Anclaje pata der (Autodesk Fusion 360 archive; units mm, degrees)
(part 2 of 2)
sketch "Boceto32" plane through (0, 285, 0) normal (0, 1, 0) x axis (1, 0, 0)
  circle C1 centre (0, 0) radius 7
  circle C2 centre (0, 0) radius 5.25
  point P1 (0, 0)
  point P2 (0, 0)
  coincident P1 P2
  concentric C1 C2
  dimension "d256" diameter C1 = 14 (= "d_29")
  dimension "d257" diameter C2 = 10.5 (= "d_29_int")
sketch "Boceto33" plane through (0, 0, 0) normal (0, 0, 1) x axis (1, 0, 0)
  line L1 (47.25, -30) -> (45.5, -30)
  line L2 (45.5, -27) -> (47.25, -27)
  line L3 (50.75, -20) -> (49, -20)
  line L4 (49, -17) -> (50.75, -17)
  line L5 (54.25, -10) -> (52.5, -10)
  line L6 (52.5, -7) -> (54.25, -7)
  line L7 (56, 0) -> (54.25, 0)
  line L8 (54.25, 3) -> (56, 3)
  line L9 (52.5, 10) -> (50.75, 10)
  line L10 (50.75, 13) -> (52.5, 13)
  line L11 (49, 20) -> (47.25, 20)
  line L12 (47.25, 23) -> (49, 23)
  line L13 (45.5, 30) -> (43.75, 30)
  line L14 (43.75, 33) -> (45.5, 33)
  line L15 (43.75, 40) -> (42, 40)
  line L16 (42, 43) -> (43.75, 43)
  line L17 (42, 50) -> (40.25, 50)
  line L18 (40.25, 53) -> (42, 53)
  line L19 (40.25, 60) -> (38.5, 60)
  line L20 (38.5, 63) -> (40.25, 63)
  line L21 (38.5, 70) -> (36.75, 70)
  line L22 (36.75, 73) -> (38.5, 73)
  line L23 (29.75, 80) -> (28, 80)
  line L24 (28, 83) -> (29.75, 83)
  line L25 (22.75, 90) -> (21, 90)
  line L26 (21, 93) -> (22.75, 93)
  line L27 (45.5, -30) -> (47.25, -30)
  line L28 (45.5, -27) -> (45.5, -30)
  line L29 (49, -20) -> (50.75, -20)
  line L30 (49, -17) -> (49, -20)
  line L31 (50.75, -17) -> (49, -17)
  line L32 (52.5, -10) -> (54.25, -10)
  line L33 (52.5, -10) -> (54.25, -10)
  line L34 (52.5, -7) -> (52.5, -10)
  line L35 (54.25, 0) -> (56, 0)
  line L36 (54.25, 0) -> (56, 0)
  line L37 (54.25, 3) -> (54.25, 0)
  line L38 (50.75, 10) -> (52.5, 10)
  line L39 (50.75, 13) -> (50.75, 10)
  line L40 (47.25, 20) -> (49, 20)
  line L41 (43.75, 30) -> (45.5, 30)
  line L42 (43.75, 33) -> (43.75, 30)
  line L43 (42, 40) -> (43.75, 40)
  line L44 (42, 43) -> (42, 40)
  line L45 (40.25, 50) -> (42, 50)
  line L46 (38.5, 60) -> (40.25, 60)
  line L47 (38.5, 63) -> (40.25, 63)
  line L48 (36.75, 70) -> (38.5, 70)
  line L49 (36.75, 73) -> (36.75, 70)
  line L50 (38.5, 60) -> (38.5, 63)
  line L51 (40.25, 53) -> (40.25, 50)
  line L52 (38.5, 73) -> (36.75, 75)
  line L53 (28, 80) -> (29.75, 80)
  line L54 (29.75, 83) -> (28, 85)
  line L55 (21, 90) -> (22.75, 90)
  line L56 (21, 93) -> (21, 90)
  line L57 (28, 83) -> (28, 80)
  line L58 (47.25, 23) -> (47.25, 20)
  line L59 (17, 88) -> (17, 90)
  line L60 (41.5, -32) -> (41.5, -25)
  line L61 (2, 90) -> (2, 95)
  line L62 (17, 90) -> (2, 90)
  line L63 (2, 100) -> (2, 95)
  line L64 (5, 100) -> (2, 100)
  line L65 (5, 96) -> (5, 100)
  line L66 (41.5, -37) -> (41.5, -32)
  line L67 (44.5, -37) -> (41.5, -37)
  line L68 (45.5, -37) -> (44.5, -37)
  line L69 (47.25, -38.2302) -> (47.25, -30)
  line L70 (47.25, -37) -> (45.5, -37)
  arc A1 centre (-131.6173, -3.3783) radius 174.4624 clockwise from (17, 88) to (41.5, -25)
  arc A2 centre (-12.1249, 48.1252) radius 54.4955 clockwise from (22.75, 90) to (29.75, 83)
  arc A3 centre (19.2917, 57.9584) radius 24.3969 clockwise from (29.75, 80) to (38.5, 73)
  arc A4 centre (-26.7489, 49.969) radius 68.2544 clockwise from (38.5, 70) to (40.25, 63)
  arc A5 centre (-76.2927, 27.1457) radius 121.0852 clockwise from (40.25, 60) to (42, 53)
  arc A6 centre (22.875, 41.5) radius 20.9289 clockwise from (42, 50) to (43.75, 43)
  arc A7 centre (-1.5, 24.9688) radius 47.6812 clockwise from (43.75, 40) to (45.5, 33)
  arc A8 centre (19.0393, 12.3947) radius 31.7823 clockwise from (45.5, 30) to (49, 23)
  arc A9 centre (-15.6248, -16.6874) radius 74.3124 clockwise from (49, 20) to (52.5, 13)
  arc A10 centre (40.625, -0.3125) radius 15.7278 clockwise from (52.5, 10) to (56, 3)
  arc A11 centre (21.7396, 4.8464) radius 34.6015 clockwise from (56, 0) to (54.25, -7)
  arc A12 centre (24.9327, 0.2836) radius 31.0686 clockwise from (54.25, -10) to (50.75, -17)
  arc A13 centre (-15.8334, 8.9167) radius 72.5915 clockwise from (50.75, -20) to (47.25, -27)
  arc A14 centre (4.1403, 36.9029) radius 59.1033 clockwise from (5, 96) to (22.75, 93)
  point P52 (28, 85)
  point P50 (36.75, 75)
  point P84 (47.25, -37)
  point P2 (47.25, -30)
  point P3 (47.25, -27)
  point P28 (45.5, -30)
  point P8 (56, 0)
  point P35 (54.25, 0)
  point P10 (52.5, 10)
  point P37 (50.75, 10)
  point P12 (49, 20)
  point P39 (47.25, 20)
  point P14 (45.5, 30)
  point P40 (43.75, 30)
  point P18 (42, 50)
  point P44 (40.25, 50)
  point P22 (38.5, 70)
  point P47 (36.75, 70)
  horizontal L1
  perpendicular L2 L28
  perpendicular L4 L30
  perpendicular L6 L34
  perpendicular L8 L37
  perpendicular L10 L39
  perpendicular L14 L42
  perpendicular L16 L44
  perpendicular L22 L49
  perpendicular L19 L50
  perpendicular L18 L51
  perpendicular L26 L56
  perpendicular L24 L57
  perpendicular L12 L58
  coincident P52 A2
  coincident P50 A3
  perpendicular L59 L62
  perpendicular L63 L64
  perpendicular L66 L67
  perpendicular L27 L69
  coincident L69 P84
  perpendicular L69 L70
  dimension "d262" distance P2 P3 = 3
  dimension "d263" distance P2 P28 = 1.75
  dimension "d272" distance P8 P35 = 1.75
  dimension "d275" distance P10 P37 = 1.75
  dimension "d280" distance P12 P39 = 1.75
  dimension "d285" distance P14 P40 = 1.75
  dimension "d288" distance P18 P44 = 1.75
  dimension "d291" distance P22 P47 = 1.75
sketch "Boceto34" plane through (0, 93, 0) normal (0, 1, 0) x axis (-1, 0, 0)
  line L1 (-185, 110) -> (-160, 110)
  line L2 (-160, 85) -> (-160, 110)
  line L3 (-135, 110) -> (-160, 110)
  line L4 (-160, 135) -> (-160, 110)
  line L5 (-184.8747, 107.5) -> (-160, 107.5)
  line L6 (-184.8747, 112.5) -> (-160, 112.5)
  line L7 (-162.5, 85.1253) -> (-162.5, 110)
  line L8 (-157.5, 85.1253) -> (-157.5, 110)
  line L9 (-135.1253, 107.5) -> (-160, 107.5)
  line L10 (-135.1253, 112.5) -> (-160, 112.5)
  line L11 (-162.5, 134.8747) -> (-162.5, 110)
  line L12 (-157.5, 134.8747) -> (-157.5, 110)
  circle C1 centre (-160, 110) radius 21
  circle C2 centre (-160, 110) radius 22.75
  circle C3 centre (-160, 110) radius 21
  circle C4 centre (-160, 110) radius 2.5
  circle C5 centre (-160, 110) radius 22.75
  circle C6 centre (-160, 110) radius 25
  point P6 (-160, 110)
  point P7 (-160, 110)
  point P8 (-185, 110)
  point P3 (-160, 110)
  point P9 (-160, 110)
  point P10 (-160, 85)
  point P5 (-160, 110)
  point P11 (-160, 110)
  point P12 (-135, 110)
  point P13 (-160, 135)
  point P14 (-160, 107.5)
  point P15 (-184.8747, 107.5)
  point P16 (-160, 112.5)
  point P17 (-184.8747, 112.5)
  point P18 (-162.5, 110)
  point P19 (-162.5, 85.1253)
  point P20 (-157.5, 110)
  point P21 (-157.5, 85.1253)
  point P22 (-135.1253, 107.5)
  point P23 (-135.1253, 112.5)
  point P24 (-162.5, 134.8747)
  point P25 (-157.5, 134.8747)
  tangent C1 C3
  concentric C3 C4
  concentric C4 C5
  concentric C4 C6
  coincident P6 P7
  coincident C6 P8
  horizontal L1
  coincident P3 P9
  coincident C6 P10
  perpendicular L1 L2
  coincident P5 P11
  coincident C6 P12
  perpendicular L2 L3
  coincident C6 P13
  perpendicular L3 L4
  coincident C4 P14
  coincident L2 P14
  coincident C6 P15
  tangent C4 L5
  coincident C4 P16
  coincident L4 P16
  coincident C6 P17
  tangent C4 L6
  coincident C4 P18
  coincident L1 P18
  coincident C6 P19
  tangent C4 L7
  coincident C4 P20
  coincident L3 P20
  coincident C6 P21
  tangent C4 L8
  coincident C6 P22
  horizontal L9
  coincident C6 P23
  parallel L9 L10
  coincident C6 P24
  perpendicular L10 L11
  coincident C6 P25
  vertical L12
  dimension "d294" diameter C4 = 5
  dimension "d297" diameter C6 = 50
extrude "Extruir31" new body sketch "Boceto34" profile of C4 along normal blind 10

design "pilares_anillos_baimax"
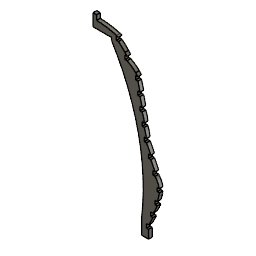
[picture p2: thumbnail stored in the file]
part number: 2026-07-06-18-36-34-739
parameter "d_1" = 112
parameter "d_1_int" = 108.5 (= "d_1 - 3.5 mm")
parameter "h_1" = -10
parameter "d_2" = 108.5
parameter "d_2_int" = 105 (= "d_2 - 3.5 mm")
parameter "h_2" = 10
parameter "h_3" = -20
parameter "h_4" = 20
parameter "h_5" = -30
parameter "h_6" = 30
parameter "h_7" = 40
parameter "d_3" = 105 (= "d_2_int")
parameter "d_3_int" = 101.5 (= "d_3 - 3.5 mm")
parameter "d_4" = 101.5 (= "d_3_int")
parameter "d_4_int" = 98 (= "d_4 - 3.5 mm")
parameter "d_5" = 98 (= "d_4_int")
parameter "d_5_int" = 94.5 (= "d_5 - 3.5 mm")
parameter "d_6" = 94.5 (= "d_5_int")
parameter "d_6_int" = 91 (= "d_6 - 3.5 mm")
parameter "d_7" = 91 (= "d_6_int")
parameter "d_7_int" = 87.5 (= "d_7 - 3.5 mm")
parameter "d_8" = 87.5 (= "d_7_int")
parameter "d_8_int" = 84 (= "d_8 - 3.5 mm")
parameter "h_8" = 50
parameter "h_9" = 60
parameter "h_10" = 70
parameter "h_11" = 110
parameter "h_12" = 120
parameter "h_13" = 130
parameter "h_14" = 140
parameter "h_15" = 80
parameter "d_9" = 84 (= "d_8_int")
parameter "d_9_int" = 80.5 (= "d_9 - 3.5 mm")
parameter "d_10" = 80.5 (= "d_9_int")
parameter "d_10_int" = 77 (= "d_10 - 3.5 mm")
parameter "d_11" = 77 (= "d_10_int")
parameter "d_11_int" = 73.5 (= "d_11 - 3.5 mm")
parameter "d_12" = 73.5 (= "d_11_int")
parameter "d_12_int" = 70 (= "d_12 - 3.5 mm")
parameter "d_13" = 70 (= "d_12_int")
parameter "d_13_int" = 66.5 (= "d_13 - 3.5 mm")
parameter "d_14" = 66.5 (= "d_13_int")
parameter "d_14_int" = 63 (= "d_14 - 3.5 mm")
parameter "d_15" = 63 (= "d_14_int")
parameter "d_15_int" = 59.5 (= "d_15 - 3.5 mm")
parameter "d_16" = 59.5 (= "d_15_int")
parameter "d_16_int" = 56 (= "d_16 - 3.5 mm")
parameter "h_16" = 160
parameter "h_17" = 170
parameter "h_18" = 180
parameter "h_19" = 90
parameter "h_20" = 200
parameter "d_17" = 56 (= "d_16_int")
parameter "d_17_int" = 52.5 (= "d_17 - 3.5 mm")
parameter "d_18" = 52.5 (= "d_17_int")
parameter "d_18_int" = 49 (= "d_18 - 3.5 mm")
parameter "d_19" = 49 (= "d_18_int")
parameter "d_19_int" = 45.5 (= "d_19 - 3.5 mm")
parameter "d_20" = 45.5 (= "d_19_int")
parameter "d_20_int" = 42 (= "d_20 - 3.5 mm")
parameter "d_21" = 42 (= "d_20_int")
parameter "d_21_int" = 38.5 (= "d_21 - 3.5 mm")
parameter "h_21" = 210
parameter "h_22" = 220
parameter "h_23" = 295
parameter "h_24" = 295
parameter "h_25" = 300
parameter "h_26" = 290
parameter "h_27" = 305
parameter "h_28" = 285
parameter "d_22" = 38.5 (= "d_21_int")
parameter "d_22_int" = 35 (= "d_22 - 3.5 mm")
parameter "d_23" = 35 (= "d_22_int")
parameter "d_23_int" = 31.5 (= "d_23 - 3.5 mm")
parameter "d_24" = 31.5 (= "d_23_int")
parameter "d_24_int" = 28 (= "d_24 - 3.5 mm")
parameter "d_25" = 28 (= "d_24_int")
parameter "d_25_int" = 24.5 (= "d_25 - 3.5 mm")
parameter "d_26" = 24.5 (= "d_25_int")
parameter "d_26_int" = 21 (= "d_26 - 3.5 mm")
parameter "d_27" = 21 (= "d_26_int")
parameter "d_27_int" = 17.5 (= "d_27 - 3.5 mm")
parameter "d_28" = 17.5 (= "d_27_int")
parameter "d_28_int" = 14 (= "d_28 - 3.5 mm")
parameter "d_29" = 14 (= "d_28_int")
parameter "d_29_int" = 10.5 (= "d_29 - 3.5 mm")
sketch "Boceto1" plane through (0, 0, 0) normal (0, 1, 0) x axis (1, 0, 0)
  circle C1 centre (0, 0) radius 56
  circle C2 centre (0, 0) radius 54.25
  point P1 (0, 0)
  point P2 (0, 0)
  coincident P1 P2
  concentric C1 C2
  dimension "d1" diameter C1 = 112 (= "d_1")
  dimension "d2" diameter C2 = 108.5 (= "d_1_int")
work_plane "PlanoDeObra2" AlongDistance -10 (= "h_1")
sketch "Boceto3" plane through (0, -10, 0) normal (0, 1, 0) x axis (1, 0, 0)
  circle C1 centre (0, 0) radius 54.25
  circle C2 centre (0, 0) radius 52.5
  point P1 (0, 0)
  point P2 (0, 0)
  coincident P1 P2
  concentric C1 C2
  dimension "d12" diameter C2 = 105 (= "d_2_int")
  dimension "d13" diameter C1 = 108.5 (= "d_2")
work_plane "PlanoDeObra3" AlongDistance 0
work_plane "PlanoDeObra4" AlongDistance 10 (= "h_2")
sketch "Boceto4" plane through (0, 10, 0) normal (0, 1, 0) x axis (1, 0, 0)
  circle C1 centre (0, 0) radius 52.5
  circle C2 centre (0, 0) radius 50.75
  point P1 (0, 0)
  point P2 (0, 0)
  point P3 (0, 0)
  coincident P1 P2
  coincident P1 P3
  dimension "d26" diameter C1 = 105 (= "d_3")
  dimension "d27" diameter C2 = 101.5 (= "d_3_int")
work_plane "PlanoDeObra5" AlongDistance -20 (= "h_3")
sketch "Boceto5" plane through (0, -20, 0) normal (0, 1, 0) x axis (1, 0, 0)
  circle C1 centre (0, 0) radius 50.75
  circle C2 centre (0, 0) radius 49
  point P1 (0, 0)
  point P2 (0, 0)
  point P3 (0, 0)
  coincident P1 P2
  coincident P1 P3
  dimension "d41" diameter C1 = 101.5 (= "d_4")
  dimension "d42" diameter C2 = 98 (= "d_4_int")
work_plane "PlanoDeObra6" AlongDistance 20 (= "h_4")
sketch "Boceto6" plane through (0, 20, 0) normal (0, 1, 0) x axis (1, 0, 0)
  circle C1 centre (0, 0) radius 49
  circle C2 centre (0, 0) radius 47.25
  point P1 (0, 0)
  point P2 (0, 0)
  coincident P1 P2
  concentric C1 C2
  dimension "d46" diameter C1 = 98 (= "d_5")
  dimension "d47" diameter C2 = 94.5 (= "d_5_int")
work_plane "PlanoDeObra7" AlongDistance -30 (= "h_5")
sketch "Boceto7" plane through (0, -30, 0) normal (0, 1, 0) x axis (1, 0, 0)
  circle C1 centre (0, 0) radius 47.25
  circle C2 centre (0, 0) radius 45.5
  point P1 (0, 0)
  point P2 (0, 0)
  coincident P1 P2
  concentric C1 C2
  dimension "d51" diameter C1 = 94.5 (= "d_6")
  dimension "d52" diameter C2 = 91 (= "d_6_int")
work_plane "PlanoDeObra8" AlongDistance 30 (= "h_6")
sketch "Boceto9" plane through (0, 30, 0) normal (0, 1, 0) x axis (1, 0, 0)
  circle C1 centre (0, 0) radius 45.5
  circle C2 centre (0, 0) radius 43.75
  point P1 (0, 0)
  point P2 (0, 0)
  point P3 (0, 0)
  coincident P1 P2
  coincident P1 P3
  dimension "d56" diameter C1 = 91 (= "d_7")
  dimension "d57" diameter C2 = 87.5 (= "d_7_int")
work_plane "PlanoDeObra9" AlongDistance 40 (= "h_7")
sketch "Boceto10" plane through (0, 40, 0) normal (0, 1, 0) x axis (1, 0, 0)
  circle C1 centre (0, 0) radius 43.75
  circle C2 centre (0, 0) radius 42
  point P1 (0, 0)
  point P2 (0, 0)
  coincident P1 P2
  concentric C1 C2
  dimension "d61" diameter C1 = 87.5 (= "d_8")
  dimension "d62" diameter C2 = 84 (= "d_8_int")
work_plane "PlanoDeObra10" AlongDistance 50 (= "h_8")
sketch "Boceto11" plane through (0, 50, 0) normal (0, 1, 0) x axis (1, 0, 0)
  circle C1 centre (0, 0) radius 42
  circle C2 centre (0, 0) radius 40.25
  point P1 (0, 0)
  point P2 (0, 0)
  coincident P1 P2
  concentric C1 C2
  dimension "d90" diameter C1 = 84 (= "d_9")
  dimension "d91" diameter C2 = 80.5 (= "d_9_int")
work_plane "PlanoDeObra11" AlongDistance 60 (= "h_9")
sketch "Boceto12" plane through (0, 60, 0) normal (0, 1, 0) x axis (1, 0, 0)
  circle C1 centre (0, 0) radius 40.25
  circle C2 centre (0, 0) radius 38.5
  point P1 (0, 0)
  point P2 (0, 0)
  point P3 (0, 0)
  coincident P1 P2
  coincident P1 P3
  dimension "d95" diameter C1 = 80.5 (= "d_10")
  dimension "d96" diameter C2 = 77 (= "d_10_int")
work_plane "PlanoDeObra12" AlongDistance 70 (= "h_10")
sketch "Boceto13" plane through (0, 70, 0) normal (0, 1, 0) x axis (1, 0, 0)
  circle C1 centre (0, 0) radius 38.5
  circle C2 centre (0, 0) radius 36.75
  point P1 (0, 0)
  point P2 (0, 0)
  point P3 (0, 0)
  coincident P1 P2
  coincident P1 P3
  dimension "d100" diameter C1 = 77 (= "d_11")
  dimension "d101" diameter C2 = 73.5 (= "d_11_int")
work_plane "PlanoDeObra13" AlongDistance 110 (= "h_11")
sketch "Boceto14" plane through (0, 110, 0) normal (0, 1, 0) x axis (1, 0, 0)
  circle C1 centre (0, 0) radius 36.75
  circle C2 centre (0, 0) radius 35
  point P1 (0, 0)
  point P2 (0, 0)
  coincident P1 P2
  concentric C1 C2
  dimension "d105" diameter C1 = 73.5 (= "d_12")
  dimension "d106" diameter C2 = 70 (= "d_12_int")
work_plane "PlanoDeObra14" AlongDistance 120 (= "h_12")
sketch "Boceto15" plane through (0, 120, 0) normal (0, 1, 0) x axis (1, 0, 0)
  circle C1 centre (0, 0) radius 35
  circle C2 centre (0, 0) radius 33.25
  point P1 (0, 0)
  point P2 (0, 0)
  coincident P1 P2
  concentric C1 C2
  dimension "d110" diameter C1 = 70 (= "d_13")
  dimension "d111" diameter C2 = 66.5 (= "d_13_int")
work_plane "PlanoDeObra15" AlongDistance 130 (= "h_13")
sketch "Boceto16" plane through (0, 130, 0) normal (0, 1, 0) x axis (1, 0, 0)
  circle C1 centre (0, 0) radius 33.25
  circle C2 centre (0, 0) radius 31.5
  point P1 (0, 0)
  point P2 (0, 0)
  coincident P1 P2
  concentric C1 C2
  dimension "d115" diameter C1 = 66.5 (= "d_14")
  dimension "d116" diameter C2 = 63 (= "d_14_int")
work_plane "PlanoDeObra17" AlongDistance 140 (= "h_14")
sketch "Boceto17" plane through (0, 140, 0) normal (0, 1, 0) x axis (1, 0, 0)
  circle C1 centre (0, 0) radius 31.5
  circle C2 centre (0, 0) radius 29.75
  point P1 (0, 0)
  point P2 (0, 0)
  point P3 (0, 0)
  coincident P1 P2
  coincident P1 P3
  dimension "d121" diameter C1 = 63 (= "d_15")
  dimension "d122" diameter C2 = 59.5 (= "d_15_int")
work_plane "PlanoDeObra18" AlongDistance 80 (= "h_15")
sketch "Boceto18" plane through (0, 80, 0) normal (0, 1, 0) x axis (1, 0, 0)
  circle C1 centre (0, 0) radius 29.75
  circle C2 centre (0, 0) radius 28
  point P1 (0, 0)
  point P2 (0, 0)
  point P3 (0, 0)
  coincident P1 P2
  coincident P1 P3
  dimension "d126" diameter C1 = 59.5 (= "d_16")
  dimension "d127" diameter C2 = 56 (= "d_16_int")
work_plane "PlanoDeObra19" AlongDistance 160 (= "h_16")
sketch "Boceto19" plane through (0, 160, 0) normal (0, 1, 0) x axis (1, 0, 0)
  circle C1 centre (0, 0) radius 28
  circle C2 centre (0, 0) radius 26.25
  point P1 (0, 0)
  point P2 (0, 0)
  coincident P1 P2
  concentric C1 C2
  dimension "d162" diameter C1 = 56 (= "d_17")
  dimension "d163" diameter C2 = 52.5 (= "d_17_int")
work_plane "PlanoDeObra20" AlongDistance 170 (= "h_17")
sketch "Boceto20" plane through (0, 170, 0) normal (0, 1, 0) x axis (1, 0, 0)
  circle C1 centre (0, 0) radius 26.25
  circle C2 centre (0, 0) radius 24.5
  point P1 (0, 0)
  point P2 (0, 0)
  coincident P1 P2
  concentric C1 C2
  dimension "d167" diameter C1 = 52.5 (= "d_18")
  dimension "d168" diameter C2 = 49 (= "d_18_int")
work_plane "PlanoDeObra21" AlongDistance 180 (= "h_18")
sketch "Boceto21" plane through (0, 180, 0) normal (0, 1, 0) x axis (1, 0, 0)
  circle C1 centre (0, 0) radius 24.5
  circle C2 centre (0, 0) radius 22.75
  point P1 (0, 0)
  point P2 (0, 0)
  point P3 (0, 0)
  coincident P1 P2
  coincident P1 P3
  dimension "d172" diameter C1 = 49 (= "d_19")
  dimension "d173" diameter C2 = 45.5 (= "d_19_int")
work_plane "PlanoDeObra22" AlongDistance 90 (= "h_19")
sketch "Boceto22" plane through (0, 90, 0) normal (0, 1, 0) x axis (1, 0, 0)
  circle C1 centre (0, 0) radius 22.75
  circle C2 centre (0, 0) radius 21
  point P1 (0, 0)
  point P2 (0, 0)
  point P3 (0, 0)
  coincident P1 P2
  coincident P1 P3
  dimension "d177" diameter C1 = 45.5 (= "d_20")
  dimension "d178" diameter C2 = 42 (= "d_20_int")
work_plane "PlanoDeObra24" AlongDistance 200 (= "h_20")
sketch "Boceto24" plane through (0, 200, 0) normal (0, 1, 0) x axis (1, 0, 0)
  circle C1 centre (0, 0) radius 21
  circle C2 centre (0, 0) radius 19.25
  point P1 (0, 0)
  point P2 (0, 0)
  point P3 (0, 0)
  coincident P1 P2
  coincident P1 P3
  dimension "d187" diameter C1 = 42 (= "d_21")
  dimension "d188" diameter C2 = 38.5 (= "d_21_int")
work_plane "PlanoDeObra25" AlongDistance 210 (= "h_21")
sketch "Boceto25" plane through (0, 210, 0) normal (0, 1, 0) x axis (1, 0, 0)
  circle C1 centre (0, 0) radius 19.25
  circle C2 centre (0, 0) radius 17.5
  point P1 (0, 0)
  point P2 (0, 0)
  coincident P1 P2
  concentric C1 C2
  dimension "d220" diameter C1 = 38.5 (= "d_22")
  dimension "d221" diameter C2 = 35 (= "d_22_int")
work_plane "PlanoDeObra26" AlongDistance 220 (= "h_22")
sketch "Boceto26" plane through (0, 220, 0) normal (0, 1, 0) x axis (1, 0, 0)
  circle C1 centre (0, 0) radius 17.5
  circle C2 centre (0, 0) radius 15.75
  point P1 (0, 0)
  point P2 (0, 0)
  coincident P1 P2
  concentric C1 C2
  dimension "d225" diameter C1 = 35 (= "d_23")
  dimension "d226" diameter C2 = 31.5 (= "d_23_int")
work_plane "PlanoDeObra28" AlongDistance 295 (= "h_23")
sketch "Boceto27" plane through (0, 295, 0) normal (0, 1, 0) x axis (1, 0, 0)
  circle C1 centre (0, 0) radius 15.75
  circle C2 centre (0, 0) radius 14
  point P1 (0, 0)
  point P2 (0, 0)
  coincident P1 P2
  concentric C1 C2
  dimension "d231" diameter C1 = 31.5 (= "d_24")
  dimension "d232" diameter C2 = 28 (= "d_24_int")
work_plane "PlanoDeObra29" AlongDistance 295 (= "h_24")
sketch "Boceto28" plane through (0, 295, 0) normal (0, 1, 0) x axis (1, 0, 0)
  circle C1 centre (0, 0) radius 14
  circle C2 centre (0, 0) radius 12.25
  point P1 (0, 0)
  point P2 (0, 0)
  point P3 (0, 0)
  coincident P1 P2
  coincident P1 P3
  dimension "d236" diameter C1 = 28 (= "d_25")
  dimension "d237" diameter C2 = 24.5 (= "d_25_int")
work_plane "PlanoDeObra30" AlongDistance 300 (= "h_25")
sketch "Boceto29" plane through (0, 300, 0) normal (0, 1, 0) x axis (1, 0, 0)
  circle C1 centre (0, 0) radius 12.25
  circle C2 centre (0, 0) radius 10.5
  point P1 (0, 0)
  point P2 (0, 0)
  coincident P1 P2
  concentric C1 C2
  dimension "d241" diameter C1 = 24.5 (= "d_26")
  dimension "d242" diameter C2 = 21 (= "d_26_int")
work_plane "PlanoDeObra31" AlongDistance 290 (= "h_26")
sketch "Boceto30" plane through (0, 290, 0) normal (0, 1, 0) x axis (1, 0, 0)
  circle C1 centre (0, 0) radius 10.5
  circle C2 centre (0, 0) radius 8.75
  point P1 (0, 0)
  point P2 (0, 0)
  point P3 (0, 0)
  coincident P1 P2
  coincident P1 P3
  dimension "d246" diameter C1 = 21 (= "d_27")
  dimension "d247" diameter C2 = 17.5 (= "d_27_int")
work_plane "PlanoDeObra32" AlongDistance 305 (= "h_27")
sketch "Boceto31" plane through (0, 305, 0) normal (0, 1, 0) x axis (1, 0, 0)
  circle C1 centre (0, 0) radius 8.75
  circle C2 centre (0, 0) radius 7
  point P1 (0, 0)
  point P2 (0, 0)
  coincident P1 P2
  concentric C1 C2
  dimension "d251" diameter C1 = 17.5 (= "d_28")
  dimension "d252" diameter C2 = 14 (= "d_28_int")
work_plane "PlanoDeObra33" AlongDistance 285 (= "h_28")
sketch "Boceto32" plane through (0, 285, 0) normal (0, 1, 0) x axis (1, 0, 0)
  circle C1 centre (0, 0) radius 7
  circle C2 centre (0, 0) radius 5.25
  point P1 (0, 0)
  point P2 (0, 0)
  coincident P1 P2
  concentric C1 C2
  dimension "d256" diameter C1 = 14 (= "d_29")
  dimension "d257" diameter C2 = 10.5 (= "d_29_int")
sketch "Boceto33" plane through (0, 0, 0) normal (0, 0, 1) x axis (1, 0, 0)
  line L1 (47.25, -30) -> (45.5, -30)
  line L2 (45.5, -27) -> (47.25, -27)
  line L3 (50.75, -20) -> (49, -20)
  line L4 (49, -17) -> (50.75, -17)
  line L5 (54.25, -10) -> (52.5, -10)
  line L6 (52.5, -7) -> (54.25, -7)
  line L7 (56, 0) -> (54.25, 0)
  line L8 (54.25, 3) -> (56, 3)
  line L9 (52.5, 10) -> (50.75, 10)
  line L10 (50.75, 13) -> (52.5, 13)
  line L11 (49, 20) -> (47.25, 20)
  line L12 (47.25, 23) -> (49, 23)
  line L13 (45.5, 30) -> (43.75, 30)
  line L14 (43.75, 33) -> (45.5, 33)
  line L15 (43.75, 40) -> (42, 40)
  line L16 (42, 43) -> (43.75, 43)
  line L17 (42, 50) -> (40.25, 50)
  line L18 (40.25, 53) -> (42, 53)
  line L19 (40.25, 60) -> (38.5, 60)
  line L20 (38.5, 63) -> (40.25, 63)
  line L21 (38.5, 70) -> (36.75, 70)
  line L22 (36.75, 73) -> (38.5, 73)
  line L23 (29.75, 80) -> (28, 80)
  line L24 (28, 83) -> (29.75, 83)
  line L25 (22.75, 90) -> (21, 90)
  line L26 (21, 93) -> (22.75, 93)
  line L27 (45.5, -30) -> (47.25, -30)
  line L28 (45.5, -27) -> (45.5, -30)
  line L29 (49, -20) -> (50.75, -20)
  line L30 (49, -17) -> (49, -20)
  line L31 (50.75, -17) -> (49, -17)
  line L32 (52.5, -10) -> (54.25, -10)
  line L33 (52.5, -10) -> (54.25, -10)
  line L34 (52.5, -7) -> (52.5, -10)
  line L35 (54.25, 0) -> (56, 0)
  line L36 (54.25, 0) -> (56, 0)
  line L37 (54.25, 3) -> (54.25, 0)
  line L38 (50.75, 10) -> (52.5, 10)
  line L39 (50.75, 13) -> (50.75, 10)
  line L40 (47.25, 20) -> (49, 20)
  line L41 (43.75, 30) -> (45.5, 30)
  line L42 (43.75, 33) -> (43.75, 30)
  line L43 (42, 40) -> (43.75, 40)
  line L44 (42, 43) -> (42, 40)
  line L45 (40.25, 50) -> (42, 50)
  line L46 (38.5, 60) -> (40.25, 60)
  line L47 (38.5, 63) -> (40.25, 63)
  line L48 (36.75, 70) -> (38.5, 70)
  line L49 (36.75, 73) -> (36.75, 70)
  line L50 (38.5, 60) -> (38.5, 63)
  line L51 (40.25, 53) -> (40.25, 50)
  line L52 (38.5, 73) -> (36.75, 75)
  line L53 (28, 80) -> (29.75, 80)
  line L54 (29.75, 83) -> (28, 85)
  line L55 (21, 90) -> (22.75, 90)
  line L56 (21, 93) -> (21, 90)
  line L57 (28, 83) -> (28, 80)
  line L58 (47.25, 23) -> (47.25, 20)
  line L59 (17, 88) -> (17, 90)
  line L60 (41.5, -32) -> (41.5, -25)
  line L61 (2, 90) -> (2, 95)
  line L62 (17, 90) -> (2, 90)
  line L63 (2, 100) -> (2, 95)
  line L64 (5, 100) -> (2, 100)
  line L65 (5, 96) -> (5, 100)
  line L66 (41.5, -37) -> (41.5, -32)
  line L67 (44.5, -37) -> (41.5, -37)
  line L68 (45.5, -37) -> (44.5, -37)
  line L69 (47.25, -38.2302) -> (47.25, -30)
  line L70 (47.25, -37) -> (45.5, -37)
  arc A1 centre (-131.6173, -3.3783) radius 174.4624 clockwise from (17, 88) to (41.5, -25)
  arc A2 centre (-12.1249, 48.1252) radius 54.4955 clockwise from (22.75, 90) to (29.75, 83)
  arc A3 centre (19.2917, 57.9584) radius 24.3969 clockwise from (29.75, 80) to (38.5, 73)
  arc A4 centre (-26.7489, 49.969) radius 68.2544 clockwise from (38.5, 70) to (40.25, 63)
  arc A5 centre (-76.2927, 27.1457) radius 121.0852 clockwise from (40.25, 60) to (42, 53)
  arc A6 centre (22.875, 41.5) radius 20.9289 clockwise from (42, 50) to (43.75, 43)
  arc A7 centre (-1.5, 24.9688) radius 47.6812 clockwise from (43.75, 40) to (45.5, 33)
  arc A8 centre (19.0393, 12.3947) radius 31.7823 clockwise from (45.5, 30) to (49, 23)
  arc A9 centre (-15.6248, -16.6874) radius 74.3124 clockwise from (49, 20) to (52.5, 13)
  arc A10 centre (40.625, -0.3125) radius 15.7278 clockwise from (52.5, 10) to (56, 3)
  arc A11 centre (21.7396, 4.8464) radius 34.6015 clockwise from (56, 0) to (54.25, -7)
  arc A12 centre (24.9327, 0.2836) radius 31.0686 clockwise from (54.25, -10) to (50.75, -17)
  arc A13 centre (-15.8334, 8.9167) radius 72.5915 clockwise from (50.75, -20) to (47.25, -27)
  arc A14 centre (4.1403, 36.9029) radius 59.1033 clockwise from (5, 96) to (22.75, 93)
  point P52 (28, 85)
  point P50 (36.75, 75)
  point P84 (47.25, -37)
  point P2 (47.25, -30)
  point P3 (47.25, -27)
  point P28 (45.5, -30)
  point P8 (56, 0)
  point P35 (54.25, 0)
  point P10 (52.5, 10)
  point P37 (50.75, 10)
  point P12 (49, 20)
  point P39 (47.25, 20)
  point P14 (45.5, 30)
  point P40 (43.75, 30)
  point P18 (42, 50)
  point P44 (40.25, 50)
  point P22 (38.5, 70)
  point P47 (36.75, 70)
  horizontal L1
  perpendicular L2 L28
  perpendicular L4 L30
  perpendicular L6 L34
  perpendicular L8 L37
  perpendicular L10 L39
  perpendicular L14 L42
  perpendicular L16 L44
  perpendicular L22 L49
  perpendicular L19 L50
  perpendicular L18 L51
  perpendicular L26 L56
  perpendicular L24 L57
  perpendicular L12 L58
  coincident P52 A2
  coincident P50 A3
  perpendicular L59 L62
  perpendicular L63 L64
  perpendicular L66 L67
  perpendicular L27 L69
  coincident L69 P84
  perpendicular L69 L70
  dimension "d262" distance P2 P3 = 3
  dimension "d263" distance P2 P28 = 1.75
  dimension "d272" distance P8 P35 = 1.75
  dimension "d275" distance P10 P37 = 1.75
  dimension "d280" distance P12 P39 = 1.75
  dimension "d285" distance P14 P40 = 1.75
  dimension "d288" distance P18 P44 = 1.75
  dimension "d291" distance P22 P47 = 1.75
sketch "Boceto34" plane through (0, 93, 0) normal (0, 1, 0) x axis (-1, 0, 0)
  line L1 (-185, 110) -> (-160, 110)
  line L2 (-160, 85) -> (-160, 110)
  line L3 (-135, 110) -> (-160, 110)
  line L4 (-160, 135) -> (-160, 110)
  line L5 (-184.8747, 107.5) -> (-160, 107.5)
  line L6 (-184.8747, 112.5) -> (-160, 112.5)
  line L7 (-162.5, 85.1253) -> (-162.5, 110)
  line L8 (-157.5, 85.1253) -> (-157.5, 110)
  line L9 (-135.1253, 107.5) -> (-160, 107.5)
  line L10 (-135.1253, 112.5) -> (-160, 112.5)
  line L11 (-162.5, 134.8747) -> (-162.5, 110)
  line L12 (-157.5, 134.8747) -> (-157.5, 110)
  circle C1 centre (-160, 110) radius 21
  circle C2 centre (-160, 110) radius 22.75
  circle C3 centre (-160, 110) radius 21
  circle C4 centre (-160, 110) radius 2.5
  circle C5 centre (-160, 110) radius 22.75
  circle C6 centre (-160, 110) radius 25
  point P6 (-160, 110)
  point P7 (-160, 110)
  point P8 (-185, 110)
  point P3 (-160, 110)
  point P9 (-160, 110)
  point P10 (-160, 85)
  point P5 (-160, 110)
  point P11 (-160, 110)
  point P12 (-135, 110)
  point P13 (-160, 135)
  point P14 (-160, 107.5)
  point P15 (-184.8747, 107.5)
  point P16 (-160, 112.5)
  point P17 (-184.8747, 112.5)
  point P18 (-162.5, 110)
  point P19 (-162.5, 85.1253)
  point P20 (-157.5, 110)
  point P21 (-157.5, 85.1253)
  point P22 (-135.1253, 107.5)
  point P23 (-135.1253, 112.5)
  point P24 (-162.5, 134.8747)
  point P25 (-157.5, 134.8747)
  tangent C1 C3
  concentric C3 C4
  concentric C4 C5
  concentric C4 C6
  coincident P6 P7
  coincident C6 P8
  horizontal L1
  coincident P3 P9
  coincident C6 P10
  perpendicular L1 L2
  coincident P5 P11
  coincident C6 P12
  perpendicular L2 L3
  coincident C6 P13
  perpendicular L3 L4
  coincident C4 P14
  coincident L2 P14
  coincident C6 P15
  tangent C4 L5
  coincident C4 P16
  coincident L4 P16
  coincident C6 P17
  tangent C4 L6
  coincident C4 P18
  coincident L1 P18
  coincident C6 P19
  tangent C4 L7
  coincident C4 P20
  coincident L3 P20
  coincident C6 P21
  tangent C4 L8
  coincident C6 P22
  horizontal L9
  coincident C6 P23
  parallel L9 L10
  coincident C6 P24
  perpendicular L10 L11
  coincident C6 P25
  vertical L12
  dimension "d294" diameter C4 = 5
  dimension "d297" diameter C6 = 50
extrude "Extruir" new body sketch "Boceto33" along normal blind 3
